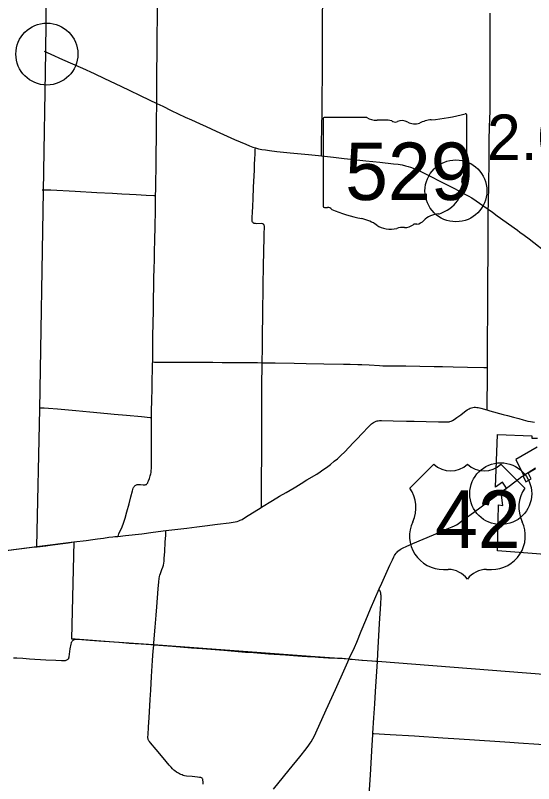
# Model space of a CAD drawing. Extents: x 1813937 to 1948437, y 826606 to 1022856.
# Drawn here: x 1840375 to 1852920, y 901785 to 920400 of the extents above; entities that cross this region are included whole.
import ezdxf

# ---------------------------------------------------------------- set-up
doc = ezdxf.new("R2010")
doc.units = 0
for name, color, linetype in [('Default', 7, 'Continuous'), ('GM_X_Corporation', 7, 'Continuous'), ('GM_X_County', 7, 'Continuous'), ('GM_X_County_Road', 7, 'Continuous'), ('GM_X_State_Route', 7, 'Continuous'), ('GM_X_State_Shield', 7, 'Continuous'), ('GM_X_Township', 7, 'Continuous'), ('GM_X_Township_Road', 7, 'Continuous'), ('GM_X_US_Route', 7, 'Continuous'), ('GM_X_US_Shield', 7, 'Continuous')]:
    doc.layers.add(name, color=color, linetype=linetype)

msp = doc.modelspace()

# ---------------------------------------------------------------- linework, layer by layer
at = {"layer": 'Default'}
for centre in [(1841137, 919463), (1851040, 916148), (1852124, 908811)]:
    msp.add_circle(centre, 750, dxfattribs=at)
at = {"layer": 'GM_X_Corporation'}
for points in [[(1854029, 907271), (1852043, 907428), (1852066, 908538), (1852177, 908528), (1852134, 908843), (1852262, 908941), (1852164, 909086), (1852000, 908971), (1852045, 910245), (1852879, 910216), (1852877, 910158), (1853013, 910154)], [(1853006, 909935), (1852486, 909635), (1852684, 909247), (1852665, 909234), (1852734, 909095), (1852863, 909170), (1852790, 909313), (1852966, 909419)]]:
    msp.add_lwpolyline(points, dxfattribs=at)
at = {"layer": 'GM_X_County'}
msp.add_lwpolyline([(1839634, 907367), (1840896, 907530), (1840970, 910855), (1841058, 916141), (1841113, 919520), (1841192, 926713), (1841249, 932050), (1841362, 942439)], dxfattribs=at)
at = {"layer": 'GM_X_County_Road'}
for points in [[(1843798, 918263), (1843797, 918443), (1843801, 919017), (1843806, 919509), (1843808, 919788), (1843810, 920017), (1843812, 920247), (1843817, 920623)], [(1851823, 915703), (1851824, 915795), (1851827, 915928), (1851832, 916223), (1851836, 916437), (1851840, 916748), (1851842, 917076), (1851847, 917388), (1851856, 917683), (1851863, 917913), (1851865, 918060), (1851868, 918241), (1851870, 918536), (1851869, 918717), (1851868, 919110), (1851869, 919373), (1851869, 919701), (1851869, 919996), (1851869, 920177), (1851870, 920258), (1851869, 920455)], [(1846335, 908486), (1846602, 908646), (1846771, 908747), (1846926, 908839), (1847123, 908956), (1847166, 908980), (1847291, 909058), (1847431, 909144), (1847670, 909287), (1847753, 909339), (1847821, 909386), (1847904, 909446), (1848000, 909518), (1848094, 909595), (1848171, 909657), (1848195, 909678), (1848255, 909735), (1848347, 909828), (1848552, 910041), (1848631, 910124), (1848778, 910278), (1848914, 910421), (1848972, 910478), (1848996, 910500), (1849022, 910521), (1849046, 910539), (1849074, 910555), (1849105, 910568), (1849135, 910576), (1849156, 910578), (1849189, 910581), (1849238, 910582), (1849517, 910575), (1849845, 910568), (1850025, 910564), (1850320, 910559), (1850615, 910553), (1850779, 910548), (1850828, 910549), (1850861, 910552), (1850877, 910555), (1850893, 910559), (1850924, 910571), (1850953, 910585), (1850995, 910611), (1851062, 910658), (1851155, 910725), (1851248, 910793), (1851315, 910840), (1851357, 910866), (1851386, 910881), (1851417, 910894), (1851447, 910902), (1851477, 910907), (1851514, 910905), (1851546, 910902), (1851579, 910897), (1851642, 910881), (1851791, 910839)], [(1851791, 910839), (1851863, 910819), (1852180, 910732), (1852290, 910702), (1852433, 910665), (1852559, 910629), (1852670, 910599), (1852781, 910571), (1852845, 910556), (1852894, 910548), (1852941, 910544)], [(1844020, 907915), (1844165, 907934), (1844311, 907951), (1844523, 907976), (1844767, 908006), (1844962, 908031), (1845271, 908070), (1845548, 908104), (1845645, 908118), (1845694, 908126), (1845742, 908138), (1845788, 908154), (1845818, 908167), (1845862, 908189), (1845946, 908240), (1846321, 908477), (1846335, 908486)], [(1842859, 907776), (1843042, 907796), (1843433, 907840), (1843709, 907876), (1844020, 907915)], [(1841792, 907640), (1842086, 907679), (1842248, 907701), (1842361, 907716), (1842507, 907736), (1842637, 907754), (1842734, 907766), (1842783, 907770), (1842859, 907776)], [(1839641, 907367), (1839743, 907381), (1840149, 907433), (1840782, 907511), (1840900, 907526)], [(1840900, 907526), (1841114, 907551), (1841268, 907569)], [(1841268, 907569), (1841276, 907570), (1841649, 907621), (1841792, 907640)], [(1849140, 904747), (1849151, 904932), (1849192, 905669), (1849218, 906144), (1849227, 906307), (1849227, 906329), (1849226, 906347), (1849225, 906371), (1849223, 906385), (1849221, 906399), (1849219, 906406), (1849214, 906422), (1849202, 906452), (1849197, 906465), (1849193, 906476), (1849182, 906502)], [(1841738, 905210), (1841744, 905225), (1841753, 905239), (1841764, 905251), (1841776, 905262), (1841790, 905271), (1841804, 905278), (1841820, 905283), (1841836, 905286), (1841869, 905286), (1841984, 905277), (1842180, 905262), (1842393, 905246), (1842884, 905209), (1843129, 905192), (1843424, 905171), (1843653, 905154), (1843723, 905149)], [(1840326, 904836), (1840408, 904832), (1840555, 904823), (1840719, 904812), (1841112, 904788), (1841358, 904774), (1841489, 904767), (1841538, 904767), (1841571, 904769), (1841587, 904772), (1841603, 904777), (1841618, 904783), (1841633, 904791), (1841647, 904800), (1841660, 904810), (1841668, 904821), (1841673, 904834), (1841676, 904854), (1841686, 904919), (1841705, 905049), (1841725, 905162), (1841732, 905195), (1841737, 905210), (1841738, 905210)], [(1843723, 905149), (1843850, 905140), (1844177, 905115), (1844635, 905078), (1844897, 905058), (1845420, 905017), (1845944, 904974), (1846140, 904960), (1846320, 904946), (1846500, 904933), (1846910, 904905), (1847106, 904892), (1847319, 904877), (1847450, 904869), (1847548, 904862), (1847712, 904849), (1847954, 904835), (1848047, 904830), (1848171, 904827), (1848285, 904823), (1848367, 904817), (1848432, 904810), (1848455, 904806)], [(1848455, 904806), (1848481, 904802), (1848511, 904797), (1848775, 904775), (1849004, 904757), (1849102, 904750), (1849140, 904747)], [(1849028, 903004), (1849051, 903376), (1849073, 903720), (1849093, 904015), (1849132, 904620), (1849140, 904747)], [(1848803, 899489), (1848805, 899500), (1848812, 899560), (1848824, 899707), (1848844, 900018), (1848868, 900395), (1848879, 900591), (1848896, 900853), (1848922, 901263), (1848968, 902000), (1849011, 902721), (1849025, 902966), (1849028, 903004)]]:
    msp.add_lwpolyline(points, dxfattribs=at)
at = {"layer": 'GM_X_State_Route'}
for points in [[(1841073, 919533), (1841234, 919461), (1841519, 919333), (1841999, 919118), (1842283, 918989), (1842536, 918872), (1842789, 918753), (1843115, 918596), (1843410, 918453), (1843798, 918263), (1843942, 918197), (1844146, 918098), (1844486, 917935), (1844636, 917868), (1844831, 917781), (1844995, 917706), (1845235, 917598), (1845683, 917395), (1845953, 917276), (1846044, 917238), (1846122, 917210), (1846185, 917190), (1846264, 917169), (1846345, 917152), (1846426, 917139), (1846524, 917125), (1846703, 917105), (1847030, 917072), (1847471, 917028), (1847715, 917003), (1847782, 916995), (1848074, 916964), (1848335, 916936), (1848564, 916912), (1848857, 916879), (1849200, 916843), (1849526, 916807), (1849640, 916792), (1849737, 916775), (1849817, 916758), (1849880, 916742), (1849943, 916722), (1850004, 916700), (1850080, 916669), (1850155, 916635), (1850272, 916577), (1850418, 916502), (1850666, 916375), (1851017, 916195), (1851192, 916104), (1851336, 916027), (1851421, 915977), (1851533, 915908), (1851614, 915853), (1851823, 915703), (1851921, 915633), (1852040, 915547), (1852533, 915192), (1852590, 915151)], [(1852590, 915151), (1852693, 915077), (1852812, 914989), (1852927, 914898), (1853042, 914804), (1853157, 914711), (1853248, 914641), (1853341, 914574), (1853450, 914500), (1853601, 914402), (1853643, 914374)]]:
    msp.add_lwpolyline(points, dxfattribs=at)
at = {"layer": 'GM_X_State_Shield'}
for p, q in [((1848880, 917927), (1847861, 917927)), ((1851307, 916874), (1851307, 917979)), ((1847827, 917890), (1847827, 915777)), ((1851307, 916874), (1851307, 916874))]:
    msp.add_line(p, q, dxfattribs=at)
for centre, major_axis, start_param, end_param in [((1847867, 917895), (40.3, 0), 1.712693, 3.28349), ((1849123, 918172), (391, 0), 4.042523, 4.731795), ((1850067, 920808), (3691, 0), 4.814394, 5.042369), ((1851269, 917984), (38.7, 0), 6.141152, 7.989035), ((1849253, 916740), (1404, 0), 1.404758, 1.657858), ((1849571, 917906), (113, 0), 3.836095, 5.185415), ((1849737, 917662), (235, 0), 0.950623, 2.079405), ((1850040, 917997), (282, 0), 4.081561, 5.145723), ((1850538, 917281), (743, 0), 1.699011, 2.107814), ((1851298, 916792), (60, 0), 1.883978, 3.671073), ((1851266, 916869), (41.5, 0), 5.05454, 6.418171), ((1850917, 916653), (360, 0), 5.934695, 6.695948), ((1851446, 916411), (262, 0), 2.387724, 3.262537), ((1850274, 916270), (923, 0), 5.101752, 6.440018), ((1847867, 915773), (40.7, 0), 3.00124, 4.508301), ((1847873, 915989), (310, 0), 4.665946, 4.897461), ((1847937, 915655), (112, 0), 0.519207, 1.627899), ((1849350, 917554), (2665, 0), 4.195997, 4.488961), ((1850663, 915184), (506, 0), 1.647645, 2.488434), ((1848555, 914828), (834, 0), 0.823519, 1.323587), ((1849457, 915645), (529, 0), 4.026481, 4.996735), ((1849802, 915486), (282, 0), 4.691044, 5.507374), ((1850057, 915282), (79.4, 0), 1.147584, 2.315152), ((1850023, 915572), (298, 0), 4.937069, 5.64225), ((1849763, 914914), (435, 0), 1.495662, 1.94098)]:
    msp.add_ellipse(centre, major_axis=major_axis, ratio=0.8, start_param=start_param, end_param=end_param, dxfattribs=at)
at = {"layer": 'GM_X_Township'}
msp.add_lwpolyline([(1840896, 907530), (1841789, 907648), (1841735, 905294), (1841826, 905293), (1842755, 905225), (1843722, 905154), (1847517, 904873), (1848451, 904813), (1848761, 904780), (1849137, 904752), (1856354, 904189)], dxfattribs=at)
at = {"layer": 'GM_X_Township_Road'}
for points in [[(1847782, 916995), (1847782, 917047), (1847783, 917162), (1847788, 917375), (1847791, 917604), (1847800, 918145), (1847802, 918342), (1847805, 918588), (1847807, 918785), (1847808, 919113), (1847807, 919326), (1847807, 919441), (1847806, 919621), (1847809, 919818), (1847809, 919933), (1847812, 920195), (1847812, 920359), (1847816, 920753), (1847818, 921179), (1847821, 921305)], [(1843771, 916033), (1843773, 916192), (1843774, 916356), (1843780, 916717), (1843785, 917110), (1843788, 917373), (1843791, 917619), (1843794, 917931), (1843797, 918177), (1843798, 918263)], [(1846138, 916134), (1846143, 916241), (1846160, 916651), (1846165, 916798), (1846169, 916913), (1846176, 917044), (1846183, 917142), (1846185, 917190)], [(1841024, 916170), (1841232, 916170), (1841822, 916138), (1842347, 916110), (1842724, 916092), (1842954, 916079), (1843134, 916069), (1843298, 916060), (1843544, 916046), (1843724, 916036), (1843741, 916035), (1843771, 916033)], [(1846351, 911985), (1846353, 912079), (1846355, 912259), (1846358, 912538), (1846360, 912784), (1846363, 913014), (1846367, 913408), (1846370, 913604), (1846371, 913719), (1846375, 913867), (1846377, 913965), (1846377, 914031), (1846379, 914162), (1846382, 914293), (1846392, 914720), (1846396, 914982), (1846400, 915130), (1846403, 915245), (1846402, 915278), (1846402, 915294), (1846399, 915312), (1846391, 915329), (1846382, 915339), (1846369, 915348), (1846354, 915353), (1846335, 915355), (1846220, 915352), (1846188, 915354), (1846171, 915356), (1846156, 915361), (1846141, 915369), (1846129, 915379), (1846118, 915392), (1846111, 915407), (1846107, 915422), (1846105, 915439), (1846106, 915472), (1846108, 915504), (1846116, 915635), (1846121, 915766), (1846130, 915963), (1846134, 916061), (1846138, 916134)], [(1843700, 912002), (1843703, 912075), (1843702, 912354), (1843704, 912633), (1843715, 913240), (1843719, 913551), (1843725, 913814), (1843730, 914043), (1843735, 914257), (1843740, 914486), (1843744, 914667), (1843748, 914962), (1843755, 915273), (1843765, 915683), (1843771, 915979), (1843771, 916033)], [(1851803, 911868), (1851804, 911941), (1851804, 912088), (1851804, 912351), (1851807, 912810), (1851808, 912941), (1851809, 913121), (1851810, 913269), (1851812, 913498), (1851812, 913711), (1851815, 914006), (1851816, 914613), (1851817, 914826), (1851818, 914941), (1851819, 915121), (1851820, 915334), (1851822, 915547), (1851823, 915646), (1851823, 915703)], [(1843673, 910654), (1843673, 910665), (1843674, 910829), (1843678, 911059), (1843683, 911370), (1843689, 911584), (1843693, 911797), (1843698, 911961), (1843700, 912002)], [(1843700, 912002), (1843742, 912001), (1844004, 911999), (1844300, 911999), (1844496, 911997), (1844726, 911996), (1844873, 911995), (1844988, 911994), (1845152, 911995), (1845382, 911993), (1845546, 911993), (1845726, 911992), (1845972, 911990), (1846071, 911988), (1846235, 911986), (1846351, 911985)], [(1846335, 908486), (1846333, 908570), (1846332, 908863), (1846331, 909077), (1846333, 909208), (1846337, 909700), (1846338, 909815), (1846342, 910192), (1846344, 910619), (1846342, 910799), (1846342, 910930), (1846343, 911177), (1846343, 911357), (1846343, 911521), (1846347, 911849), (1846351, 911985)], [(1846351, 911985), (1846431, 911984), (1846661, 911980), (1847120, 911972), (1847415, 911965), (1847842, 911958), (1848317, 911948), (1848481, 911945), (1848662, 911942), (1848760, 911939), (1848940, 911930), (1849186, 911915), (1849268, 911911), (1849366, 911910), (1849546, 911911), (1849825, 911908), (1850169, 911899), (1850514, 911892), (1850711, 911890), (1850973, 911884), (1851317, 911877), (1851711, 911869), (1851803, 911868)], [(1851791, 910839), (1851792, 910859), (1851794, 910908), (1851799, 911056), (1851801, 911531), (1851802, 911679), (1851803, 911868)], [(1840948, 910890), (1841075, 910891), (1841180, 910883), (1841393, 910865), (1841835, 910824), (1842179, 910791), (1842605, 910753), (1842769, 910737), (1843064, 910710), (1843425, 910677), (1843638, 910658), (1843673, 910654)], [(1842859, 907776), (1842868, 907806), (1842877, 907836), (1842890, 907866), (1842949, 907983), (1842969, 908028), (1842987, 908074), (1843003, 908120), (1843031, 908214), (1843076, 908372), (1843127, 908563), (1843172, 908737), (1843210, 908880), (1843219, 908912), (1843230, 908943), (1843237, 908957), (1843245, 908972), (1843254, 908986), (1843265, 908998), (1843277, 909009), (1843290, 909018), (1843305, 909025), (1843320, 909030), (1843336, 909034), (1843352, 909035), (1843368, 909035), (1843401, 909032), (1843467, 909024), (1843483, 909022), (1843500, 909023), (1843516, 909025), (1843532, 909030), (1843546, 909036), (1843559, 909046), (1843569, 909058), (1843578, 909072), (1843585, 909087), (1843597, 909118), (1843618, 909180), (1843641, 909242), (1843655, 909289), (1843662, 909321), (1843666, 909353), (1843669, 909435), (1843669, 909550), (1843670, 909697), (1843672, 910124), (1843672, 910321), (1843673, 910452), (1843673, 910654)], [(1843723, 905149), (1843725, 905182), (1843727, 905199), (1843758, 905575), (1843781, 905869), (1843797, 906066), (1843832, 906507), (1843845, 906671), (1843853, 906753), (1843861, 906801), (1843869, 906833), (1843884, 906880), (1843920, 906971), (1843943, 907033), (1843957, 907080), (1843967, 907128), (1843974, 907177), (1843980, 907242), (1843990, 907406), (1844004, 907633), (1844015, 907806), (1844019, 907886), (1844020, 907915)], [(1843619, 902807), (1843615, 902812), (1843607, 902826), (1843599, 902840), (1843592, 902855), (1843587, 902870), (1843584, 902886), (1843583, 902903), (1843583, 902919), (1843586, 902969), (1843599, 903165), (1843612, 903378), (1843637, 903821), (1843651, 904050), (1843670, 904378), (1843696, 904771), (1843712, 905001), (1843716, 905060), (1843723, 905149)], [(1849028, 903004), (1849043, 903003), (1849446, 902978), (1850036, 902940), (1850723, 902897), (1851116, 902873), (1851983, 902815), (1852342, 902790), (1852555, 902776), (1853045, 902740), (1853324, 902721), (1853977, 902672), (1854157, 902658), (1854320, 902645), (1854615, 902625), (1854843, 902609), (1855219, 902583), (1855759, 902540), (1856232, 902508)], [(1844924, 901776), (1844921, 901824), (1844916, 901875), (1844912, 901891), (1844905, 901905), (1844893, 901917), (1844879, 901925), (1844863, 901930), (1844831, 901935), (1844782, 901941), (1844651, 901954), (1844520, 901968), (1844472, 901977), (1844440, 901985), (1844409, 901995), (1844378, 902008), (1844349, 902022), (1844320, 902038), (1844279, 902064), (1844238, 902092), (1844213, 902113), (1844177, 902147), (1844143, 902183), (1844100, 902232), (1843953, 902409), (1843783, 902609), (1843646, 902773), (1843619, 902807)]]:
    msp.add_lwpolyline(points, dxfattribs=at)
at = {"layer": 'GM_X_US_Route'}
for points in [[(1852787, 909326), (1852967, 909435)], [(1852261, 908948), (1852530, 909146), (1852637, 909223), (1852666, 909244), (1852684, 909257)], [(1852684, 909257), (1852787, 909326)], [(1848455, 904806), (1848458, 904814), (1848585, 905081), (1848644, 905216), (1848745, 905476), (1848858, 905749), (1848974, 906021), (1849182, 906502), (1849247, 906642), (1849441, 907075), (1849502, 907209), (1849537, 907283), (1849553, 907312), (1849571, 907340), (1849591, 907366), (1849613, 907391), (1849636, 907415), (1849661, 907436), (1849688, 907456), (1849716, 907473), (1849760, 907496), (1849834, 907531), (1850000, 907602), (1850497, 907814), (1850828, 907956), (1850948, 908007), (1851007, 908035), (1851050, 908058), (1851092, 908084), (1851146, 908120), (1851266, 908206), (1851463, 908353), (1851647, 908489), (1851844, 908636), (1852054, 908792), (1852133, 908854)], [(1852133, 908854), (1852261, 908948)], [(1846627, 901654), (1846866, 901950), (1847000, 902116), (1847258, 902435), (1847412, 902626), (1847481, 902719), (1847513, 902766), (1847536, 902801), (1847576, 902872), (1847605, 902931), (1847649, 903020), (1847899, 903573), (1848122, 904066), (1848357, 904590), (1848455, 904806)]]:
    msp.add_lwpolyline(points, dxfattribs=at)
at = {"layer": 'GM_X_US_Shield'}
for p, q in [((1850506, 909527), (1849926, 908947)), ((1852710, 908947), (1852130, 909527)), ((1850738, 906974), (1850854, 906974)), ((1851782, 906974), (1851898, 906974))]:
    msp.add_line(p, q, dxfattribs=at)
for centre, radius, start, end in [((1850912, 909941), 580, 225.573, 314.427), ((1851724, 909941), 580, 225.573, 314.427), ((1849260, 908481), 812, 334.5471, 35.0009), ((1853375, 908481), 812, 144.9991, 205.4529), ((1850729, 907786), 812, 154.8319, 270.6383), ((1851907, 907786), 812, 269.3617, 25.1681), ((1850854, 906394), 580, 36.8699, 90), ((1851782, 906394), 580, 90, 143.1301)]:
    msp.add_arc(centre, radius, start, end, dxfattribs=at)

# ---------------------------------------------------------------- texts
at = {"layer": 'Default'}
msp.add_text('2.00', height=1100, dxfattribs=at).set_placement((1851790, 916898))
at = {"layer": 'GM_X_State_Shield'}
msp.add_text('529', height=1392.2, dxfattribs=at).set_placement((1848358, 915926))
at = {"layer": 'GM_X_US_Shield'}
msp.add_text('42', height=1392.2, dxfattribs=at).set_placement((1850534, 907496))

doc.saveas('drawing.dxf')
